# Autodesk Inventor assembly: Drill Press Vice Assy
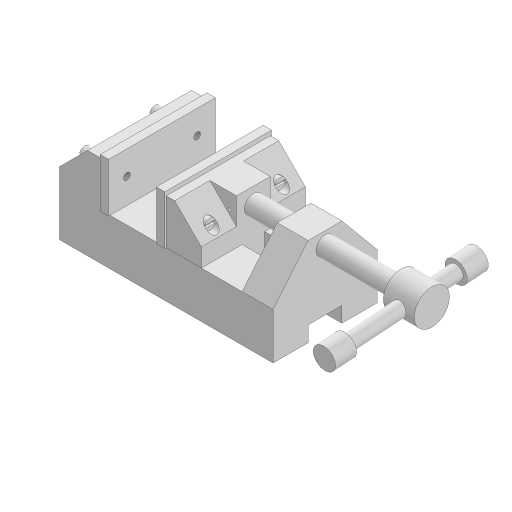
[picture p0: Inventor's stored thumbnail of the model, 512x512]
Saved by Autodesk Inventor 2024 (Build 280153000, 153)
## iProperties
Created: 2023-06
Part Number: Drill Press Vice Assy
Document SubType Name: Assembly
Designer: LENOVO-CADCIM
Author: LENOVO-CADCIM
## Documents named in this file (8)
- D:\PROJECTS\Project 2023\RESOURCES INVENTOR 2024\RESOURCES INVENTOR 2024\Inventor_2024_tut\Inventor_2024_tut\c13_Inv_2024_tut\c13_Inv_tut_2024\c13-tut02-inv\Drill Press vice\Drill Press Vice\Drill Press Vice Assy.iam
- D:\PROJECTS\Project 2023\RESOURCES INVENTOR 2024\RESOURCES INVENTOR 2024\Inventor_2024_tut\Inventor_2024_tut\c13_Inv_2024_tut\c13_Inv_tut_2024\c13-tut02-inv\Drill Press vice\Drill Press Vice\Base.ipt
- D:\PROJECTS\Project 2023\RESOURCES INVENTOR 2024\RESOURCES INVENTOR 2024\Inventor_2024_tut\Inventor_2024_tut\c13_Inv_2024_tut\c13_Inv_tut_2024\c13-tut02-inv\Drill Press vice\Drill Press Vice\Jaw Face.ipt
- D:\PROJECTS\Project 2023\RESOURCES INVENTOR 2024\RESOURCES INVENTOR 2024\Inventor_2024_tut\Inventor_2024_tut\c13_Inv_2024_tut\c13_Inv_tut_2024\c13-tut02-inv\Drill Press vice\Drill Press Vice\Movable Jaw.ipt
- D:\PROJECTS\Project 2023\RESOURCES INVENTOR 2024\RESOURCES INVENTOR 2024\Inventor_2024_tut\Inventor_2024_tut\c13_Inv_2024_tut\c13_Inv_tut_2024\c13-tut02-inv\Drill Press vice\Drill Press Vice\Cap Screw.ipt
- D:\PROJECTS\Project 2023\RESOURCES INVENTOR 2024\RESOURCES INVENTOR 2024\Inventor_2024_tut\Inventor_2024_tut\c13_Inv_2024_tut\c13_Inv_tut_2024\c13-tut02-inv\Drill Press vice\Drill Press Vice\Clamp Screw.ipt
- D:\PROJECTS\Project 2023\RESOURCES INVENTOR 2024\RESOURCES INVENTOR 2024\Inventor_2024_tut\Inventor_2024_tut\c13_Inv_2024_tut\c13_Inv_tut_2024\c13-tut02-inv\Drill Press vice\Drill Press Vice\Clamp Screw Handle.ipt
- D:\PROJECTS\Project 2023\RESOURCES INVENTOR 2024\RESOURCES INVENTOR 2024\Inventor_2024_tut\Inventor_2024_tut\c13_Inv_2024_tut\c13_Inv_tut_2024\c13-tut02-inv\Drill Press vice\Drill Press Vice\Handle Stop.ipt
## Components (12 placed, 7 different names)
1. Base:1 — Mate:1, Mate:2, Mate:3, Mate:4, Mate:5, Insert:5, Insert:6, Mate:7
2. Jaw Face:1 — Insert:1, Insert:2
3. Jaw Face:2 — Mate:1, Mate:2, Mate:3, Mate:6
4. Movable Jaw:1 — Mate:4, Mate:5, Mate:6, Insert:1, Insert:2, Insert:3, Insert:4, Mate:8
5. Cap Screw:1 — Insert:6
6. Cap Screw:2 — Insert:5
7. Cap Screw:3 — Insert:4
8. Cap Screw:4 — Insert:3
9. Clamp Screw:1 — Mate:7, Mate:8, Mate:10, Mate:11
10. Clamp Screw Handle:1 — Insert:7, Insert:8, Mate:11
11. Handle Stop:1 — Insert:8, Mate:10
12. Handle Stop:2 — Insert:7
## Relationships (18: Mate 10, Insert 8)
- Mate:1: Base:1 ↔ Jaw Face:2
- Mate:2: Base:1 ↔ Jaw Face:2
- Mate:3: Base:1 ↔ Jaw Face:2
- Mate:4: Base:1 ↔ Movable Jaw:1
- Mate:5: Base:1 ↔ Movable Jaw:1
- Mate:6: Jaw Face:2 ↔ Movable Jaw:1
- Insert:1: Jaw Face:1 ↔ Movable Jaw:1
- Insert:2: Jaw Face:1 ↔ Movable Jaw:1
- Insert:3: Movable Jaw:1 ↔ Cap Screw:4
- Insert:4: Movable Jaw:1 ↔ Cap Screw:3
- Insert:5: Base:1 ↔ Cap Screw:2
- Insert:6: Base:1 ↔ Cap Screw:1
- Mate:7: Base:1 ↔ Clamp Screw:1
- Mate:8: Movable Jaw:1 ↔ Clamp Screw:1
- Insert:7: Clamp Screw Handle:1 ↔ Handle Stop:2
- Insert:8: Clamp Screw Handle:1 ↔ Handle Stop:1
- Mate:10: Clamp Screw:1 ↔ Handle Stop:1
- Mate:11: Clamp Screw:1 ↔ Clamp Screw Handle:1
